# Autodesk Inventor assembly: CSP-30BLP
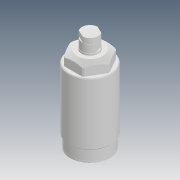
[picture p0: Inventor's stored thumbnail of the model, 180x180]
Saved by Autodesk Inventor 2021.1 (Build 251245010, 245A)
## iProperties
Created: 2019-01
Part Number: CSP-30BLP
Description: STEP AP203
Document SubType Name: Assembly
Designer: user
Title: CSP-030-P×é×°Í¼£¨³õÊ¼×´Ì¬£©.STEP
Revision Number: ÈÎºÎ
Sending System: SolidWorks 2014
Preprocessor: SwSTEP 2.0
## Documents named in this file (4)
- D:\Vault_2016\Projekty\Clamptek\Hydraulic\CSP-P-K\CSP-30KP\Inventor\CSP-30BLP\CSP-30BLP.iam
- D:\Vault_2016\Projekty\Clamptek\Hydraulic\CSP-P-K\CSP-30KP\Inventor\CSP-30BLP\CSP-030-P±¾Ìå£¨³õÊ¼£©.ipt
- D:\Vault_2016\Projekty\Clamptek\Hydraulic\CSP-P-K\CSP-30KP\Inventor\CSP-30BLP\CSP-030»îÈû¸Ë.ipt
- D:\Vault_2016\Projekty\Clamptek\Hydraulic\CSP-P-K\CSP-30KP\Inventor\CSP-30BLP\CSP-030Ô²Í·ÂÝË¨.ipt
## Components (3 placed, 3 different names)
1. CSP-030-P±¾Ìå£¨³õÊ¼£©_1
2. CSP-030»îÈû¸Ë_2
3. CSP-030Ô²Í·ÂÝË¨_3
